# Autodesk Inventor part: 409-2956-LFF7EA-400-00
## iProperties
Created: 2010-06
Part Number: 409-2956-LFF7EA-400-00
Material: 1/16"Thk PLASTIC
Document SubType Name: Modeling
Designer: S. Boerckel
Engineer: Steve Boerckel
Mass: 230.468 g
Surface Area: 3121.12 cm^2
Volume: 245.178 cm^3
Density: 0.94 g/cm^3
Description: TAG
SMR: =<Material>
Length: 20.000 in
Wide: 12.000 in
Thickness: 0.063 in
Author: S. Boerckel
Revision Number: 0
Subject: DEMIN WATER FORWARDING PUMP SKID-7EA
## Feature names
1. Extrusion1
2. Hole1
